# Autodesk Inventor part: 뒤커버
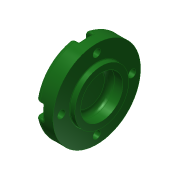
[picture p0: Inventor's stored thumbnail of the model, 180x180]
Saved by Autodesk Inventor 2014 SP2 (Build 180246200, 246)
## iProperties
Created: 2015-11
Part Number: 뒤커버
Material: 알루미늄 6061
Document SubType Name: Modeling
Designer: mduedu
Density: 1 g/cm^3
Appearance: 매끄러움 - 짙은 산림 녹색
Author: mduedu
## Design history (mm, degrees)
sketch "스케치1"
  geometry: L1 (-7, 0)-(7, 0); L2 (-7, 0)-(-7, 26); L3 (-7, 26)-(4, 26); L4 (4, 26)-(4, 16); L5 (4, 16)-(7, 16); L6 (7, 16)-(7, 0); 2 further points
  constraints: 12 end point, 3 perpendicular, 2 parallel, 1 coincident, 1 horizontal, 1 midpoint
  dimensions: "d0" = 14 distance of L1.start L1.end; "d1" = 52 diameter of L3 L1; "d2" = 3 distance of L4.end L5.end; "d3" = 32 diameter of L5 L1
revolve "회전1" sketch "스케치1" stored, may be unused: angle "d4" = 90 deg
hole "구멍1" diameter "d7" = 25; stored, may be unused: countersink angle "d11" = 90 deg, drill point angle "d13" = 0 deg; dims "d8" = 6, "d9" = 4, "d10" = 2, "d12" = 8, "d62" = 10, "d63" = 10
fillet "모깎기2" dims "d36" = 3
fillet "모깎기3" dims "d37" = 3
fillet "모깎기4" dims "d38" = 0.3
sketch "스케치3" dims "d61" = 42
  geometry: C1 r 26 at (0, 0) reference; 2 further points
  constraints: 2 vertical alignment, 1 coincident, 2 other
hole "구멍4" sketch "스케치3" at (0, -21) diameter "d44" = 4.5; stored, may be unused: countersink angle "d48" = 90 deg, drill point angle "d50" = 0 deg; dims "d45" = 6, "d46" = 8, "d47" = 4.6, "d49" = 8
sketch "스케치4"
  geometry: L1 (-4, 0)-(-4, -4.69); L2 (4, 0)-(4, -4.69); A1 r 4 centre (0, 0) between (3.614, -1.714) and (-3.614, -1.714) reference; A2 r 26 centre (0, 21) between (-4, -4.69) and (4, -4.69) reference; 1 further point
  constraints: 4 end point, 4 point on circle, 2 tangent, 1 parallel, 1 vertical
extrude "돌출1" cut sketch "스케치4" stored distance "d51" = 0; taper "d52" = 0 deg
fillet "모깎기5" dims "d56" = 0.3
fillet "모깎기6" dims "d57" = 1
node "솔리드1"
pattern_circular "원형 패턴1" dims angle "d54" = 360 deg
